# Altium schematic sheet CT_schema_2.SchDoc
size 454 x 387 mm
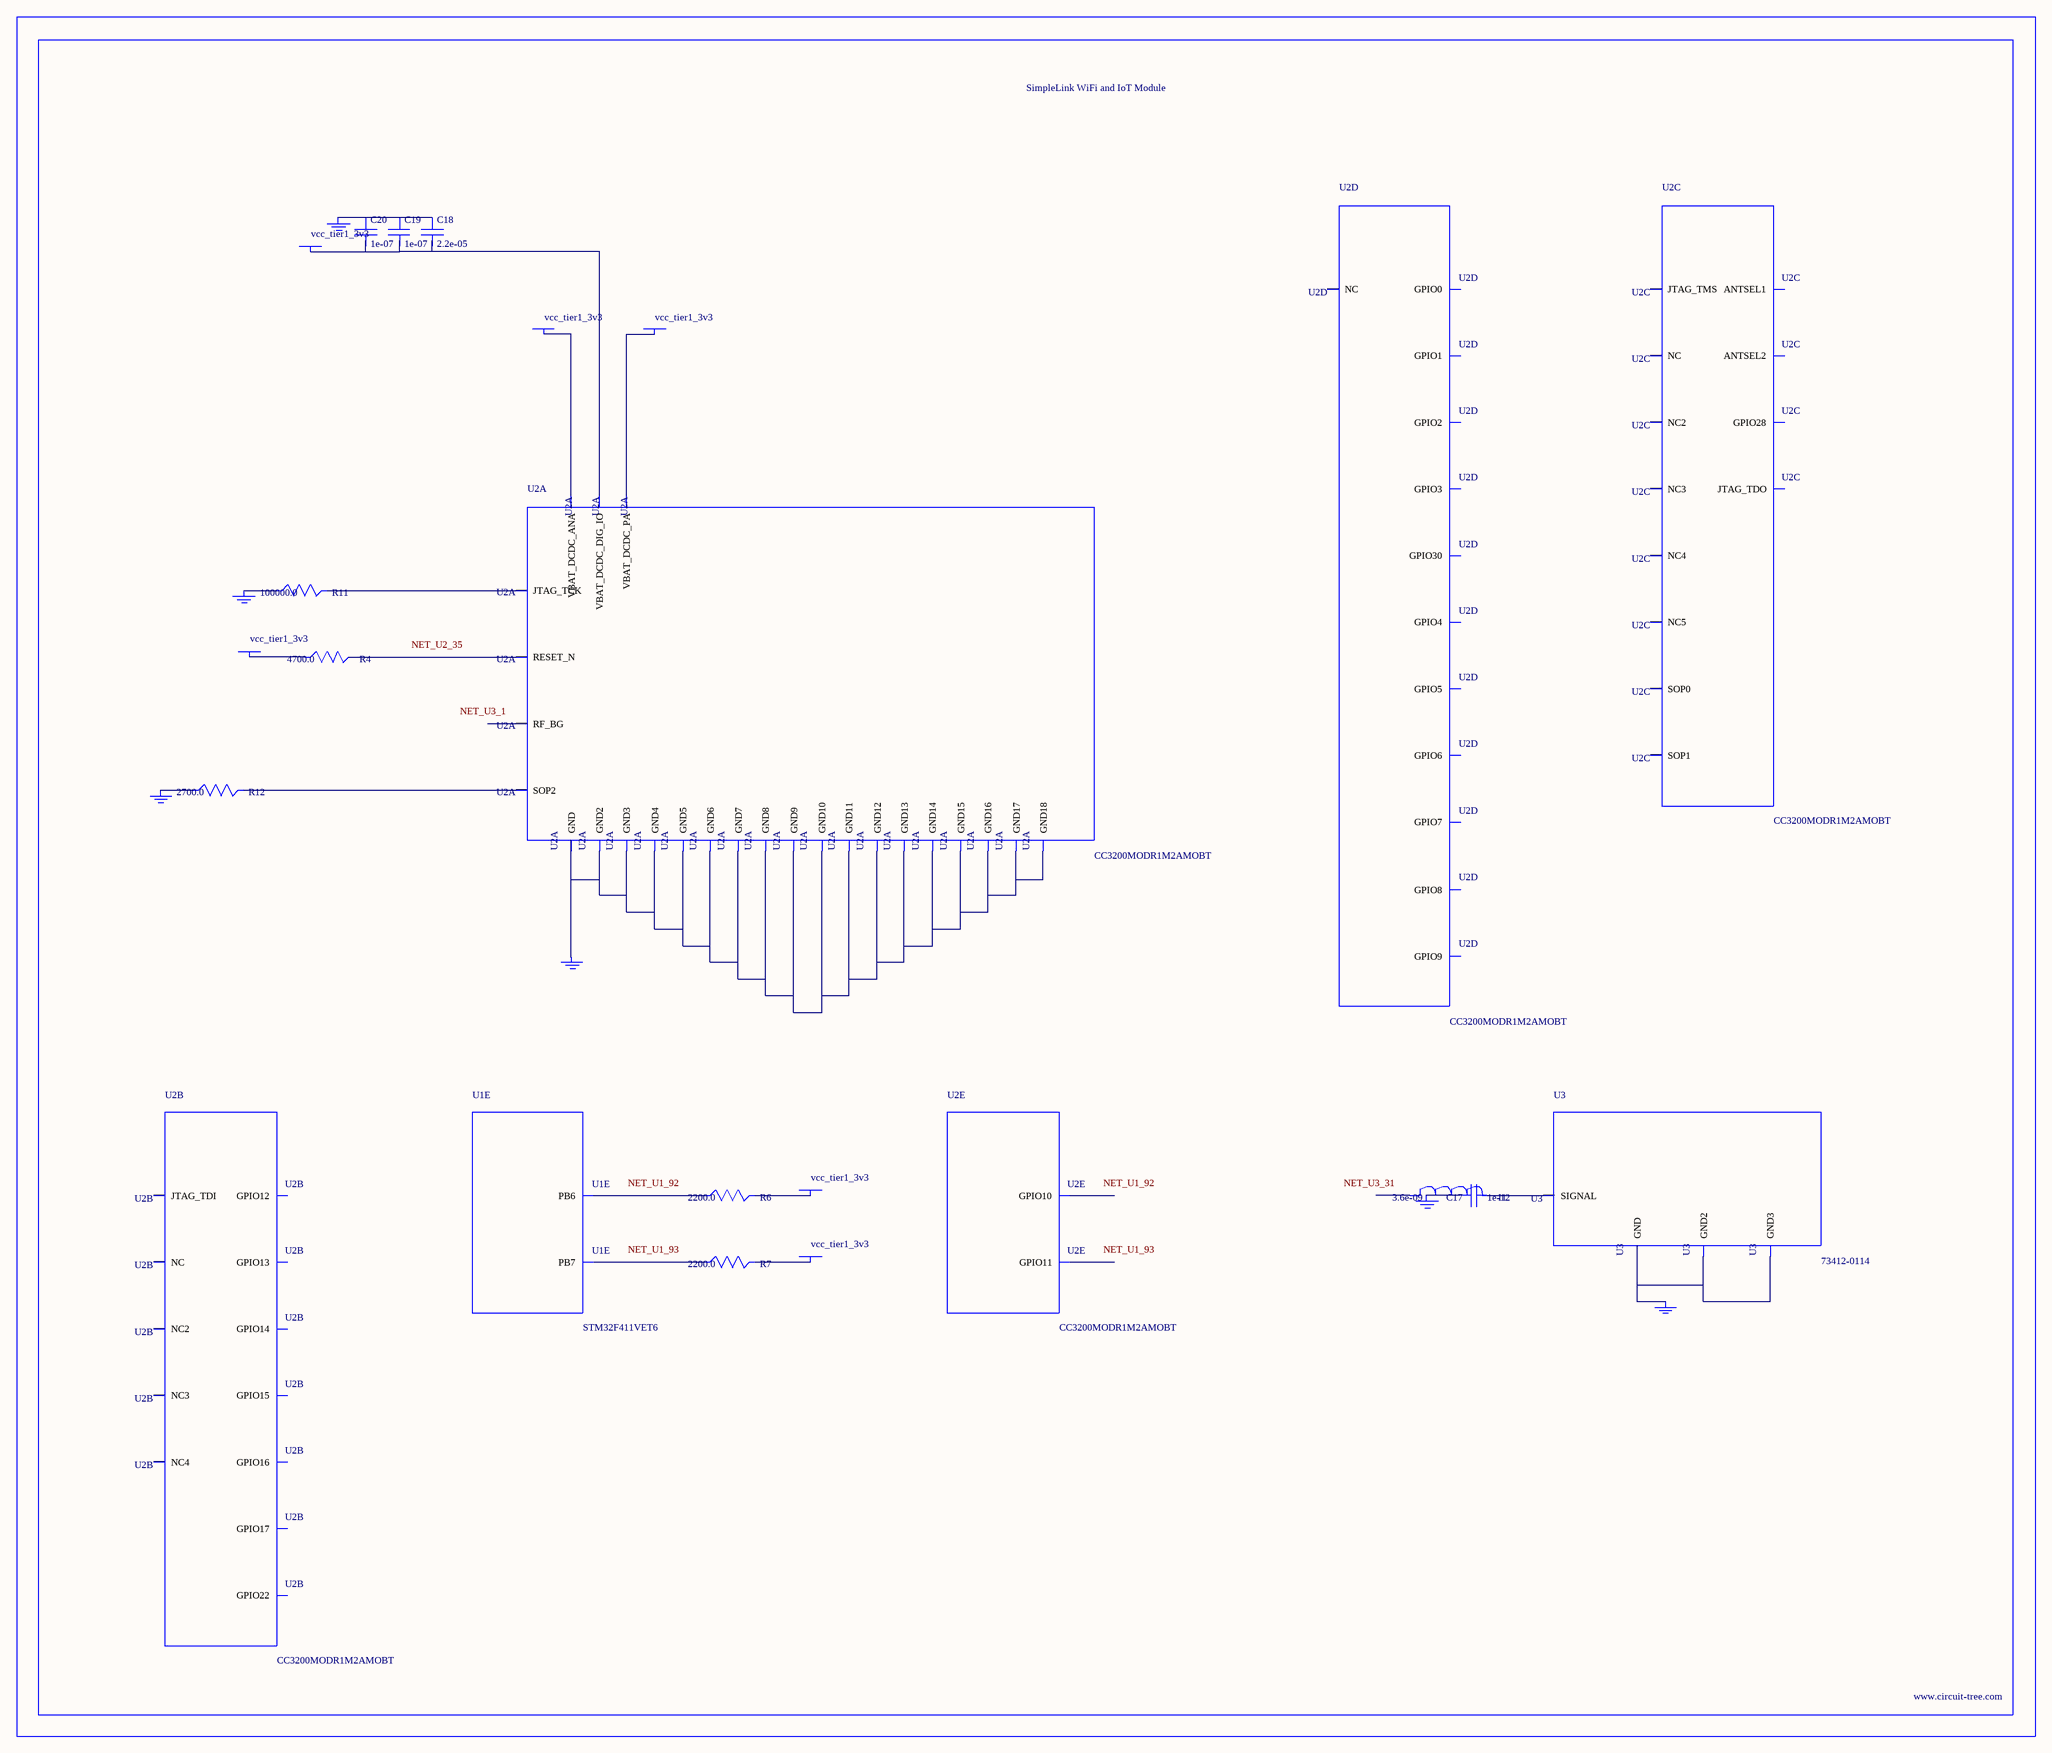
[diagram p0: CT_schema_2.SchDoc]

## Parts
BORDER1  (no value)
C17  1e-12  [C0402]
C18  2.2e-05  [C1210]
C19  1e-07  [C0402]
C20  1e-07  [C0402]
GND_INSTANCE_1_0  (no value)
GND_INSTANCE_1_1  (no value)
GND_INSTANCE_1_2  (no value)
GND_INSTANCE_1_3  (no value)
GND_INSTANCE_1_4  (no value)
GND_INSTANCE_1_5  (no value)
I1  3.6e-09  [C0402]
POWER_INSTANCE_1_0  vcc_tier1_3v3
POWER_INSTANCE_1_1  vcc_tier1_3v3
POWER_INSTANCE_1_2  vcc_tier1_3v3
POWER_INSTANCE_1_3  vcc_tier1_3v3
POWER_INSTANCE_1_4  vcc_tier1_3v3
POWER_INSTANCE_1_5  vcc_tier1_3v3
R4  4700.0  [R0603]
R6  2200.0  [R0603]
R7  2200.0  [R0603]
R11  100000.0  [R0603]
R12  2700.0  [R0603]
U1  STM32F411VET6  [LQFP100]  (part E of 10)
U2  CC3200MODR1M2AMOBT  [LGA63S127P16X13_2050X1750X150]  (parts A,B,C,D,E of 5)
U3  73412-0114  [COAXIAL_C]

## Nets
NetC17_1: C17.1 I1.2 U3.1(SIGNAL)
NetC17_2: C17.2 GND_INSTANCE_1_4.0(GND)
NetC18_1: C18.1 C19.1 C20.1 GND_INSTANCE_1_2.0(GND)
NetC18_2: C18.2 C19.2 C20.2 POWER_INSTANCE_1_2.0(PWR) U2.40(VBAT_DCDC_DIG_IO)
NetGND_INSTANCE_1_0_0: GND_INSTANCE_1_0.0(GND) R11.1
NetGND_INSTANCE_1_1_0: GND_INSTANCE_1_1.0(GND) R12.1
NetGND_INSTANCE_1_3_0: GND_INSTANCE_1_3.0(GND) U2.1(GND) U2.2(GND2) U2.16(GND3) U2.27(GND4) U2.28(GND5) U2.30(GND6) U2.32(GND7) U2.38(GND8) U2.43(GND9) U2.55(GND10) U2.56(GND11) U2.57(GND12) U2.58(GND13) U2.59(GND14) U2.60(GND15) U2.61(GND16) U2.62(GND17) U2.63(GND18)
NetGND_INSTANCE_1_5_0: GND_INSTANCE_1_5.0(GND) U3.2(GND) U3.3(GND2) U3.4(GND3)
NetPOWER_INSTANCE_1_0_0: POWER_INSTANCE_1_0.0(PWR) U2.36(VBAT_DCDC_ANA)
NetPOWER_INSTANCE_1_1_0: POWER_INSTANCE_1_1.0(PWR) U2.37(VBAT_DCDC_PA)
NetPOWER_INSTANCE_1_3_0: POWER_INSTANCE_1_3.0(PWR) R4.1
NetPOWER_INSTANCE_1_4_0: POWER_INSTANCE_1_4.0(PWR) R6.2
NetPOWER_INSTANCE_1_5_0: POWER_INSTANCE_1_5.0(PWR) R7.2
NetR4_2: R4.2 U2.35(RESET_N)
NetR6_1: R6.1 U1.92(PB6)
NetR7_1: R7.1 U1.93(PB7)
NetR11_2: R11.2 U2.21(JTAG_TCK)
NetR12_2: R12.2 U2.23(SOP2)

Not connected (* = marked no-connect by the designer): I1 1; U2 3(GPIO10) 4(GPIO11) 5(GPIO14) 6(GPIO15) 7(GPIO16) 8(GPIO17) 9(GPIO12) 10(GPIO13) 11(GPIO22) 12(JTAG_TDI) 13(NC) 14(NC2) 15(NC3) 17(NC4) 18(JTAG_TDO) 19(GPIO28) 20(NC) 22(JTAG_TMS) 24(SOP1) 25(ANTSEL1) 26(ANTSEL2) 29(NC2) 31(RF_BG) 33(NC3) 34(SOP0) 39(NC4) 41(NC5) 42(GPIO30) 44(GPIO0) 45(NC) 46(GPIO1) 47(GPIO2) 48(GPIO3) 49(GPIO4) 50(GPIO5) 51(GPIO6) 52(GPIO7) 53(GPIO8) 54(GPIO9)

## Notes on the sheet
- Labels drawn without touching a wire or pin: NET_U1_92, NET_U1_93, NET_U2_35, NET_U3_1, NET_U3_31

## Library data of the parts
BORDER1 = BORDER_PAGE1
C17 = C0402C109C3GACTU
C18 = C1210C224K5RACTU
C19 C20 = C0402C104K3RACTU
GND_INSTANCE_1_0-GND_INSTANCE_1_5 = GND
I1 = MCFT0BT3N6
POWER_INSTANCE_1_0-POWER_INSTANCE_1_5 = PWR
R4 = RC0603JR-074K7L
R6 R7 = RC0603JR-072K2L
R11 = RC0603JR-07100KL
R12 = RC0603JR-072K7L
